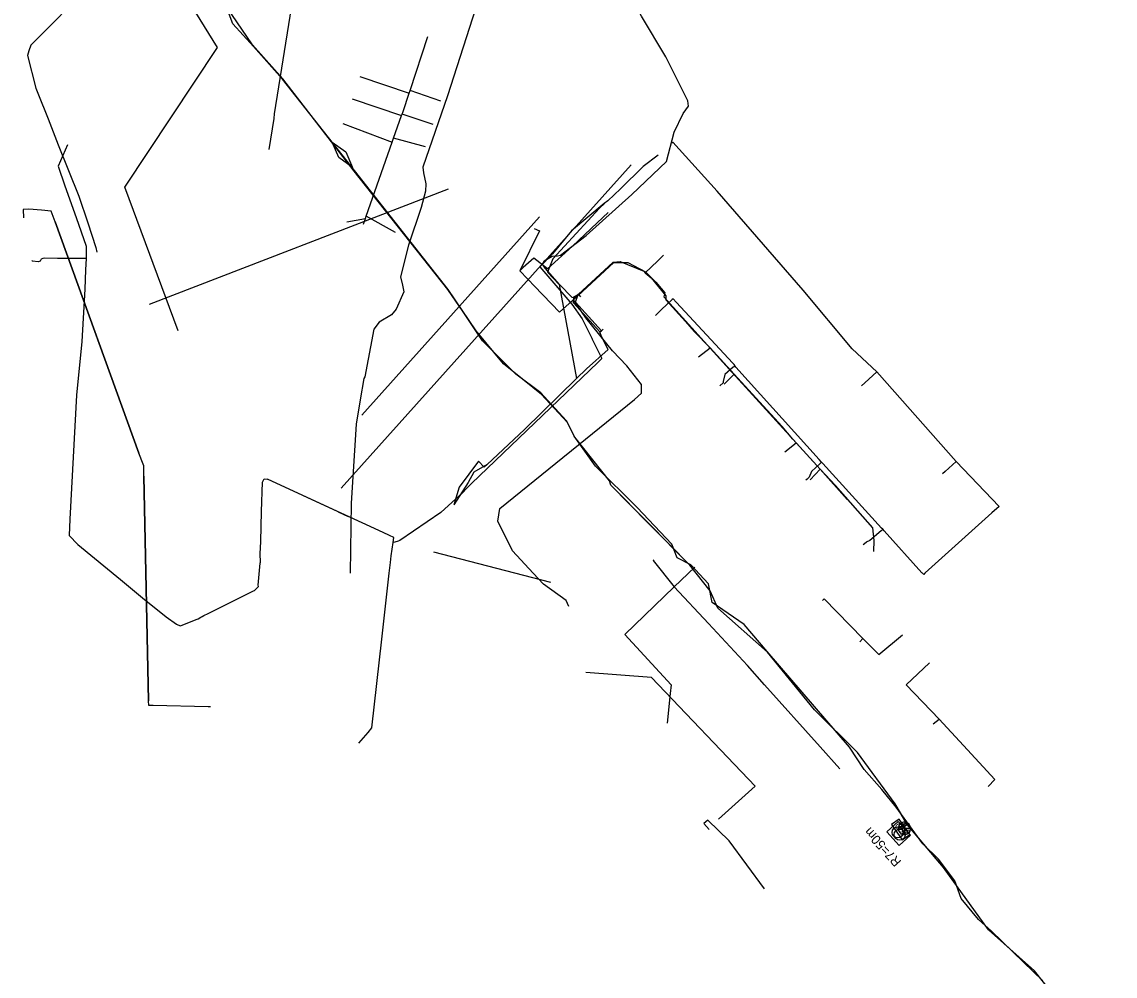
# Model space of a CAD drawing. Extents: x -748507 to -687366, y -1057342 to -1024924.
# Drawn here: x -744424.5 to -744188.5, y -1040087 to -1039880.9 of the extents above; entities that cross this region are included whole.
import ezdxf

# ---------------------------------------------------------------- set-up
doc = ezdxf.new("R2010")
doc.units = 0
for name, color, linetype in [('6kV - SŽDC', 7, 'Continuous'), ('DK + TKK - SŽDC', 7, 'Continuous'), ('Kanalizace - pražské vodovody a kanalizace', 7, 'Continuous'), ('NTL - PRAŽSKÁ PLYNÁRENSKÁ', 7, 'Continuous'), ('PRE - NN', 7, 'Continuous'), ('STL - PRAŽSKÁ PLYNÁRENSKÁ', 7, 'Continuous'), ('Telefonica O2', 7, 'Continuous'), ('TK+DOK_Pha Holešovice - Kralupy', 7, 'Continuous'), ('Vodovod - přežsko vodovody a kanalizace', 7, 'Continuous')]:
    doc.layers.add(name, color=color, linetype=linetype)

msp = doc.modelspace()

# ---------------------------------------------------------------- linework, layer by layer
at = {"layer": '6kV - SŽDC'}
for points in [[(-744368.25, -1039893.29), (-744374.48, -1039886.27), (-744378.97, -1039881.33), (-744380.56, -1039877.17), (-744384.32, -1039870.22), (-744391.86, -1039860.01), (-744394.99, -1039852.44), (-744396.08, -1039849.73), (-744402.91, -1039837.78), (-744404.95, -1039835.84), (-744408.32, -1039829.58), (-744409.64, -1039825.72), (-744411.8, -1039822.37), (-744414.1, -1039815.74), (-744417.59, -1039806.84), (-744420.96, -1039801.7), (-744422.82, -1039799.77), (-744423.64, -1039798.15), (-744424.52, -1039793.8)], [(-744326.42, -1039947.65), (-744332.5, -1039938.7), (-744355.33, -1039909.64), (-744368.25, -1039893.29)], [(-744353.16, -1039912.39), (-744356.11, -1039910.26), (-744357.5, -1039906.89), (-744354.55, -1039909.02), (-744353.16, -1039912.39)], [(-744242.63, -1040042.37), (-744245.85, -1040037.58), (-744263.57, -1040016.92), (-744268.59, -1040011.05), (-744275.48, -1040006.29), (-744276.28, -1040002.31), (-744280.07, -1039998.18), (-744283.01, -1039996.68), (-744284.21, -1039993.71), (-744291.7, -1039985.8), (-744300.69, -1039976.89), (-744305.31, -1039970.38), (-744306.8, -1039967.37), (-744312.32, -1039961.37), (-744320.56, -1039954.77), (-744326.42, -1039947.65)], [(-744204.19, -1040087.99), (-744208.25, -1040083.99), (-744215.17, -1040077.28), (-744217.99, -1040074.79), (-744221.69, -1040070.24), (-744223.08, -1040066.4), (-744226.63, -1040061.77), (-744230.03, -1040058.46), (-744235.77, -1040050.55), (-744238.86, -1040046.71), (-744242.63, -1040042.37)]]:
    msp.add_lwpolyline(points, dxfattribs=at)
at = {"layer": 'DK + TKK - SŽDC'}
for p, q in [((-744235.12, -1040053.09), (-744236.77, -1040054.25)), ((-744236.77, -1040054.25), (-744234.46, -1040057.55)), ((-744232.81, -1040056.39), (-744235.12, -1040053.09)), ((-744234.46, -1040057.55), (-744232.81, -1040056.39))]:
    msp.add_line(p, q, dxfattribs=at)
for points in [[(-744374.7, -1039885.89), (-744380.29, -1039877.76), (-744387.73, -1039866.25), (-744394.34, -1039856.01), (-744394.79, -1039852.71), (-744398.79, -1039844.27), (-744409.27, -1039827.53)], [(-744312.46, -1039961.08), (-744317.85, -1039957), (-744325.1, -1039949.82), (-744329.27, -1039943.58), (-744332.58, -1039938.75), (-744352.74, -1039913.16), (-744368.16, -1039893.24), (-744374.7, -1039885.89)], [(-744263.53, -1040017.02), (-744274.26, -1040007.58), (-744275.92, -1040003.81), (-744280.33, -1039998.25), (-744289.2, -1039989.22), (-744297.34, -1039980.99), (-744297.64, -1039980.08), (-744305.12, -1039970.61), (-744306.93, -1039967.07), (-744312.46, -1039961.08)], [(-744244.09, -1040038.7), (-744253.36, -1040029.48), (-744263.53, -1040017.02)], [(-743943.1, -1040375.98), (-743951.7, -1040366.67), (-743972.3, -1040343.88), (-744006.53, -1040306.88), (-744025.44, -1040285.45), (-744058.47, -1040248.87), (-744089.66, -1040214.01), (-744121.46, -1040179.2), (-744137.08, -1040162.07), (-744166.85, -1040129.04), (-744187.46, -1040107.76), (-744193.81, -1040101.14), (-744205.89, -1040085.9), (-744215.85, -1040077.02), (-744225.54, -1040063.55), (-744233.4, -1040054.23), (-744235.94, -1040049.83), (-744244.09, -1040038.7)], [(-744233.4, -1040054.23), (-744233.96, -1040054.74)]]:
    msp.add_lwpolyline(points, dxfattribs=at)
at = {"layer": 'Kanalizace - pražské vodovody a kanalizace'}
for p, q in [((-744369.95, -1039900.81), (-744364.16, -1039864.37)), ((-744351.52, -1039892.74), (-744340.9, -1039896.31)), ((-744334.07, -1039898.04), (-744340.71, -1039895.74)), ((-744353.17, -1039897.57), (-744342.52, -1039901.13)), ((-744335.7, -1039903.1), (-744342.42, -1039900.85)), ((-744355.23, -1039902.91), (-744344.55, -1039906.9)), ((-744337.34, -1039907.94), (-744344.25, -1039906.05)), ((-744312.38, -1039933.47), (-744292.95, -1039911.81)), ((-744396.95, -1039941.87), (-744332.39, -1039917)), ((-744354.35, -1039924.09), (-744350.33, -1039923.37)), ((-744351.15, -1039965.85), (-744312.75, -1039923.06)), ((-744343.86, -1039926.42), (-744350.16, -1039922.9)), ((-744355.57, -1039981.62), (-744312.38, -1039933.47)), ((-744279.23, -1039998.72), (-744283.66, -1040002.95)), ((-744283.66, -1040002.95), (-744294.37, -1040013.23)), ((-744276.3, -1040010.86), (-744283.66, -1040002.95)), ((-744267.85, -1040019.95), (-744276.3, -1040010.86)), ((-744294.37, -1040013.23), (-744284.34, -1040024.1)), ((-744243.61, -1040014.83), (-744242.93, -1040014.07)), ((-744242.93, -1040014.07), (-744239.5, -1040017.57)), ((-744239.5, -1040017.57), (-744234.38, -1040013.34)), ((-744233.56, -1040024.13), (-744228.54, -1040019.35)), ((-744264.15, -1040024.07), (-744267.85, -1040019.95)), ((-744284.34, -1040024.1), (-744284.52, -1040025.94)), ((-744252.13, -1040037.49), (-744264.15, -1040024.07)), ((-744226.45, -1040031.5), (-744233.56, -1040024.13)), ((-744284.52, -1040025.94), (-744285.22, -1040032.41)), ((-744227.78, -1040032.55), (-744226.45, -1040031.5)), ((-744247.91, -1040042.21), (-744252.13, -1040037.49))]:
    msp.add_line(p, q, dxfattribs=at)
for points in [[(-744390.78, -1039947.69), (-744402.3, -1039916.65), (-744382.3, -1039886.5), (-744399.85, -1039858.04)], [(-744342.22, -1039900.28), (-744340.9, -1039896.31), (-744340.71, -1039895.74), (-744336.86, -1039884.1)], [(-744371.11, -1039908.47), (-744370.08, -1039901.83), (-744369.95, -1039900.81)], [(-744350.76, -1039924.6), (-744350.33, -1039923.37), (-744350.16, -1039922.9), (-744344.55, -1039906.9), (-744344.25, -1039906.05), (-744342.52, -1039901.13), (-744342.42, -1039900.85), (-744342.22, -1039900.28)], [(-744288.06, -1039997.09), (-744288.21, -1039997.28), (-744283.66, -1040002.95)], [(-744251.64, -1040005.87), (-744251.28, -1040005.53), (-744242.93, -1040014.07)], [(-744215.86, -1040046.04), (-744214.46, -1040044.56), (-744221.18, -1040037.24), (-744226.45, -1040031.5)]]:
    msp.add_lwpolyline(points, dxfattribs=at)
at = {"layer": 'NTL - PRAŽSKÁ PLYNÁRENSKÁ'}
for p, q in [((-744417.34, -1039924.11), (-744399.23, -1039974.04)), ((-744398.17, -1039979.02), (-744397.15, -1040027.58))]:
    msp.add_line(p, q, dxfattribs=at)
for points in [[(-744398.35, -1039976.46), (-744399.23, -1039974.04), (-744417.34, -1039924.11), (-744418.18, -1039921.79), (-744420.28, -1039921.61), (-744422.98, -1039921.38), (-744424.22, -1039921.45), (-744424.18, -1039923.22)], [(-744383.78, -1040028.84), (-744384.32, -1040028.83), (-744396.14, -1040028.59), (-744397.14, -1040028.58), (-744397.15, -1040027.58), (-744398.17, -1039979.02), (-744398.22, -1039976.84), (-744398.35, -1039976.46)], [(-744264.2, -1040068.15), (-744271.84, -1040057.78), (-744276.45, -1040053.34), (-744277.26, -1040054.08), (-744276.11, -1040055.33)]]:
    msp.add_lwpolyline(points, dxfattribs=at)
at = {"layer": 'PRE - NN'}
for points in [[(-744297.94, -1039922.07), (-744300.34, -1039924.35), (-744305.67, -1039929.35), (-744311.01, -1039934.25), (-744313.97, -1039931.97), (-744316.26, -1039934.01), (-744317.02, -1039934.69)], [(-744313.89, -1039925.57), (-744312.73, -1039926.07), (-744317.02, -1039934.69)], [(-744306.4, -1040007.18), (-744306.98, -1040005.86), (-744311.91, -1040002.38), (-744314.11, -1040000), (-744318.56, -1039995.2), (-744321.75, -1039988.73), (-744321.32, -1039986.03), (-744292.28, -1039962.52), (-744290.77, -1039961.13), (-744290.71, -1039959.25), (-744293.88, -1039955.24), (-744296.99, -1039951.95), (-744302.77, -1039944.84), (-744305.4, -1039940.99), (-744296.74, -1039932.93), (-744293.7, -1039932.91), (-744289.85, -1039934.89), (-744287.62, -1039937.18), (-744285.67, -1039939.44), (-744285.91, -1039940.31), (-744271.16, -1039956.65), (-744252.15, -1039977.55), (-744246.3, -1039984.05)], [(-744317.02, -1039934.69), (-744313.69, -1039938.18), (-744312.26, -1039939.65), (-744311.97, -1039939.95), (-744308.42, -1039943.6), (-744304.3, -1039939.88), (-744303.93, -1039940.32)]]:
    msp.add_lwpolyline(points, dxfattribs=at)
at = {"layer": 'STL - PRAŽSKÁ PLYNÁRENSKÁ'}
for p, q in [((-744410.64, -1039931.09), (-744410.65, -1039932.02)), ((-744410.62, -1039930.74), (-744410.64, -1039931.09)), ((-744286.85, -1039943.47), (-744287.73, -1039944.35)), ((-744300.14, -1039954.46), (-744327.46, -1039980.63)), ((-744254.57, -1039979.29), (-744254.66, -1039979.39)), ((-744356.25, -1039986.73), (-744371.52, -1039979.66)), ((-744356.24, -1039986.73), (-744354.05, -1039987.74)), ((-744344.36, -1039993.36), (-744344.27, -1039993.34)), ((-744343.98, -1039993.26), (-744344.27, -1039993.34)), ((-744343.28, -1039993.06), (-744343.98, -1039993.26))]:
    msp.add_line(p, q, dxfattribs=at)
for points in [[(-744414.68, -1039907.51), (-744416.71, -1039912.11), (-744415.21, -1039916.31), (-744412.78, -1039923.15), (-744410.63, -1039929.34), (-744410.62, -1039930.74)], [(-744213.5, -1039985.59), (-744222.78, -1039975.84), (-744239.93, -1039956.51), (-744245.24, -1039951.55), (-744255.82, -1039938.86), (-744274.38, -1039917.48), (-744283.94, -1039906.92), (-744284.2, -1039907.12)], [(-744287.14, -1039909.7), (-744290.4, -1039912.17), (-744295.29, -1039917), (-744298.04, -1039919.6), (-744298.8, -1039920.16), (-744305.84, -1039926.05), (-744309.95, -1039931), (-744312.68, -1039933.82), (-744305.76, -1039941.92), (-744303.55, -1039945.05), (-744301.38, -1039949.41)], [(-744410.65, -1039932.02), (-744416.83, -1039932.02), (-744419.54, -1039931.99), (-744419.97, -1039932.01), (-744420.32, -1039932.16), (-744420.54, -1039932.59), (-744420.99, -1039932.73), (-744422.23, -1039932.62), (-744422.4, -1039932.49)], [(-744410.65, -1039932.02), (-744410.79, -1039934.48), (-744410.95, -1039938.65), (-744411.56, -1039949.94), (-744412.71, -1039961.54), (-744414.14, -1039988.32), (-744414.33, -1039991.88), (-744412.47, -1039993.83), (-744403.24, -1040001.34), (-744398.45, -1040005.29), (-744393.34, -1040009.4), (-744391.16, -1040011.02), (-744390.34, -1040011.37), (-744389.9, -1040011.19), (-744386.86, -1040010.01), (-744386.49, -1040009.83), (-744385.87, -1040009.51), (-744385.58, -1040009.35), (-744385.21, -1040009.14), (-744384.3, -1040008.67), (-744381.97, -1040007.58), (-744374.51, -1040003.8), (-744374.3, -1040003.71), (-744373.46, -1040002.89), (-744373.48, -1040002.57), (-744373.09, -1039997.86), (-744372.98, -1039997.64), (-744373.07, -1039995.85), (-744372.94, -1039993.17), (-744372.76, -1039986.7), (-744372.6, -1039980.37), (-744372.19, -1039979.65), (-744371.52, -1039979.66)], [(-744283.9, -1039940.74), (-744284.14, -1039940.9), (-744286.4, -1039943.02), (-744286.85, -1039943.47)], [(-744270.74, -1039954.93), (-744271.01, -1039954.63), (-744283.28, -1039941.43), (-744283.9, -1039940.74)], [(-744329.26, -1039982.47), (-744328.56, -1039981.75), (-744328.5, -1039981.68), (-744327.8, -1039980.96), (-744327.46, -1039980.63), (-744300.14, -1039954.46), (-744299.71, -1039954.04), (-744299.28, -1039953.63), (-744299.32, -1039953.54), (-744301.38, -1039949.41)], [(-744270.54, -1039955.26), (-744270.93, -1039955.51), (-744272.71, -1039957.07), (-744273.07, -1039958.58)], [(-744213.5, -1039985.59), (-744215.1, -1039986.95), (-744229.5, -1039999.93), (-744229.56, -1040000), (-744229.79, -1040000.26), (-744230.08, -1040000), (-744230.2, -1039999.9), (-744238.34, -1039990.84), (-744238.62, -1039990.49), (-744238.9, -1039990.29), (-744251.61, -1039976.28), (-744251.86, -1039976.02), (-744252.35, -1039975.44), (-744270.35, -1039955.48), (-744270.54, -1039955.26), (-744270.74, -1039954.93)], [(-744239.93, -1039956.51), (-744242.54, -1039958.89), (-744243.25, -1039959.52)], [(-744273.07, -1039958.58), (-744273.13, -1039958.86), (-744273.84, -1039959.56)], [(-744251.86, -1039976.02), (-744252.13, -1039976.31), (-744254, -1039978), (-744254.57, -1039979.29)], [(-744222.78, -1039975.84), (-744225.17, -1039978.02), (-744225.76, -1039978.57)], [(-744344.36, -1039993.36), (-744344.21, -1039992.27), (-744345.12, -1039991.85), (-744346.48, -1039991.22), (-744355.61, -1039987.03), (-744371.52, -1039979.66)], [(-744254.66, -1039979.39), (-744255, -1039979.7), (-744255.26, -1039979.93)], [(-744329.26, -1039982.47), (-744334.06, -1039986.86), (-744342.91, -1039992.94), (-744343.28, -1039993.06)], [(-744238.62, -1039990.49), (-744238.99, -1039990.85), (-744241.45, -1039992.92), (-744242.24, -1039993.33)], [(-744351.77, -1040036.67), (-744349.75, -1040034.38), (-744348.98, -1040033.41), (-744346.81, -1040014.23), (-744345.2, -1040000), (-744344.95, -1039997.72), (-744344.78, -1039996.22), (-744344.36, -1039993.36)], [(-744242.24, -1039993.33), (-744242.26, -1039993.34), (-744242.88, -1039993.89)]]:
    msp.add_lwpolyline(points, dxfattribs=at)
at = {"layer": 'Telefonica O2'}
for points in [[(-744304.3, -1039855.63), (-744305.07, -1039854.44), (-744307.1, -1039853.62), (-744311.94, -1039853.03), (-744316.56, -1039854.15), (-744319.15, -1039856.63), (-744321.44, -1039860.62), (-744323.74, -1039869.28), (-744327.19, -1039880.13), (-744332.61, -1039896.92), (-744337.94, -1039912.34), (-744337.79, -1039913.56), (-744337.28, -1039915.93), (-744337.36, -1039917.5), (-744338.34, -1039921.02), (-744341.03, -1039929.15), (-744342.79, -1039935.99), (-744342.35, -1039937.79), (-744342.05, -1039939.2), (-744343.67, -1039942.97), (-744344.7, -1039944.19), (-744347.36, -1039945.79), (-744348.5, -1039947.32), (-744350.45, -1039957.56)], [(-744304.44, -1039939.84), (-744305.26, -1039940.56), (-744305.68, -1039940.47), (-744308.46, -1039937.67), (-744311.56, -1039934.15), (-744312.14, -1039933.23), (-744311.76, -1039932.57), (-744310.02, -1039931.5), (-744308.85, -1039931.46), (-744308.22, -1039931.29), (-744302.7, -1039927.08), (-744292.8, -1039918.21), (-744285.34, -1039911.12), (-744283.65, -1039904.76), (-744281.77, -1039900.69), (-744280.6, -1039899.12), (-744280.75, -1039897.97), (-744285.49, -1039888.46), (-744290.77, -1039879.69), (-744294.83, -1039872.09), (-744298.52, -1039863.7), (-744301.65, -1039857.36), (-744303.05, -1039856.53)], [(-744298.72, -1039920.16), (-744299.81, -1039921.15)], [(-744299.81, -1039921.15), (-744309.91, -1039932.12)], [(-744285.96, -1039931.32), (-744287.27, -1039932.58), (-744289.92, -1039935.13)], [(-744309.91, -1039932.12), (-744311.03, -1039934.98), (-744308.52, -1039937.64), (-744304.74, -1039957.94)], [(-744304.44, -1039939.84), (-744296.86, -1039932.86), (-744295.33, -1039932.68), (-744290.24, -1039934.77)], [(-744287.27, -1039932.58), (-744289.92, -1039935.13)], [(-744290.24, -1039934.77), (-744289.92, -1039935.13)], [(-744289.92, -1039935.13), (-744288.67, -1039936.21), (-744285.47, -1039940.13), (-744285.45, -1039940.98), (-744281.21, -1039945.65), (-744279.35, -1039947.78), (-744275.94, -1039951.35)], [(-744308.46, -1039937.67), (-744305.68, -1039940.47)], [(-744299.7, -1039947.89), (-744305.4, -1039941.64), (-744305.33, -1039940.33), (-744304.44, -1039939.84)], [(-744299.4, -1039947.67), (-744305.01, -1039941.44), (-744304.44, -1039939.84)], [(-744304.74, -1039957.94), (-744302.61, -1039955.85), (-744297.92, -1039951.72), (-744299.34, -1039948.88), (-744299.7, -1039947.89), (-744299.4, -1039947.67)], [(-744299.4, -1039947.67), (-744299.02, -1039947.27)], [(-744278.43, -1039953.24), (-744275.94, -1039951.35)], [(-744270.7, -1039957.01), (-744275.94, -1039951.35)], [(-744350.45, -1039957.56), (-744350.69, -1039957.92), (-744351.5, -1039962.57), (-744352.31, -1039967.79), (-744353.44, -1039984.89), (-744353.65, -1040000)], [(-744304.74, -1039957.94), (-744315.97, -1039968.95)], [(-744315.97, -1039968.95), (-744304.74, -1039957.94)], [(-744270.7, -1039957.01), (-744272.91, -1039959.2)], [(-744258.05, -1039971.02), (-744260.39, -1039968.29), (-744263.57, -1039964.81), (-744270.7, -1039957.01)], [(-744315.97, -1039968.95), (-744324.03, -1039976.55), (-744326.95, -1039978.21), (-744328.13, -1039980.39), (-744331.29, -1039985.2)], [(-744315.97, -1039968.95), (-744324.03, -1039976.55), (-744324.73, -1039977.1), (-744325.96, -1039975.77), (-744330.09, -1039981.43)], [(-744259.76, -1039973.78), (-744257.31, -1039971.84)], [(-744257.31, -1039971.84), (-744258.05, -1039971.02)], [(-744252.16, -1039977.5), (-744257.31, -1039971.84)], [(-744252.16, -1039977.5), (-744254.29, -1039979.81)], [(-744240.56, -1039995.29), (-744240.49, -1039992.96), (-744240.82, -1039990.23), (-744248.85, -1039981.08), (-744252.16, -1039977.5)], [(-744330.09, -1039981.43), (-744331.29, -1039985.2)]]:
    msp.add_lwpolyline(points, dxfattribs=at)
at = {"layer": 'TK+DOK_Pha Holešovice - Kralupy'}
for p, q in [((-744235.24, -1040054.65), (-744233.95, -1040054.72)), ((-744234.88, -1040054.1), (-744233.92, -1040054.15)), ((-744236.01, -1040057.05), (-744236.03, -1040057.01)), ((-744235.32, -1040055.02), (-744235.32, -1040055.02)), ((-744235.32, -1040055.02), (-744235.32, -1040055.02)), ((-744234.03, -1040056.45), (-744234.03, -1040056.45)), ((-744234.01, -1040055.99), (-744233.01, -1040056.04)), ((-744233.98, -1040055.41), (-744232.68, -1040055.48)), ((-744232.62, -1040055.16), (-744232.62, -1040055.16)), ((-744232.62, -1040055.16), (-744232.62, -1040055.16))]:
    msp.add_line(p, q, dxfattribs=at)
for points in [[(-744374.7, -1039885.89), (-744380.29, -1039877.76), (-744387.73, -1039866.25), (-744394.34, -1039856.01), (-744394.79, -1039852.71), (-744398.79, -1039844.27), (-744409.27, -1039827.53)], [(-744225.54, -1040063.55), (-744233.23, -1040054.44), (-744235.94, -1040049.83), (-744244.09, -1040038.7), (-744253.36, -1040029.48), (-744263.53, -1040017.02), (-744274.26, -1040007.58), (-744275.92, -1040003.81), (-744280.33, -1039998.25), (-744289.2, -1039989.23), (-744297.34, -1039980.99), (-744297.64, -1039980.08), (-744305.12, -1039970.61), (-744306.93, -1039967.06), (-744312.46, -1039961.08), (-744317.85, -1039957), (-744325.1, -1039949.82), (-744329.27, -1039943.58), (-744332.57, -1039938.75), (-744352.74, -1039913.16), (-744368.16, -1039893.24), (-744374.7, -1039885.89), (-744380.29, -1039877.76)], [(-744263.53, -1040017.02), (-744274.26, -1040007.58), (-744275.92, -1040003.81), (-744280.33, -1039998.25), (-744289.2, -1039989.23), (-744297.34, -1039980.99), (-744297.64, -1039980.08), (-744305.12, -1039970.61), (-744306.93, -1039967.06), (-744312.46, -1039961.08), (-744317.85, -1039957), (-744325.1, -1039949.82), (-744329.27, -1039943.58), (-744332.57, -1039938.75), (-744352.74, -1039913.16), (-744368.16, -1039893.24), (-744374.7, -1039885.89)], [(-744235.94, -1040049.83), (-744244.09, -1040038.7), (-744253.36, -1040029.48), (-744263.53, -1040017.02)], [(-743943.1, -1040375.98), (-743951.7, -1040366.67), (-743972.3, -1040343.88), (-744006.53, -1040306.88), (-744025.44, -1040285.45), (-744058.47, -1040248.87), (-744089.66, -1040214.01), (-744121.46, -1040179.2), (-744137.08, -1040162.06), (-744166.85, -1040129.04), (-744187.46, -1040107.76), (-744193.81, -1040101.14), (-744205.89, -1040085.9), (-744215.85, -1040077.02), (-744225.54, -1040063.55), (-744233.23, -1040054.44), (-744235.94, -1040049.83)], [(-744233.9, -1040053.75), (-744233.97, -1040055.09), (-744235.32, -1040055.02)], [(-744232.62, -1040055.16), (-744233.97, -1040055.1), (-744234.03, -1040056.45)], [(-744193.81, -1040101.14), (-744205.89, -1040085.9), (-744215.85, -1040077.02), (-744225.54, -1040063.55)]]:
    msp.add_lwpolyline(points, dxfattribs=at)
msp.add_lwpolyline([(-744235.1, -1040058.81), (-744237.77, -1040055.85), (-744235.3, -1040053.62), (-744232.63, -1040056.58)], close=True, dxfattribs=at)
for centre in [(-744235.44, -1040055.97), (-744234.98, -1040056.45)]:
    msp.add_circle(centre, 1.2, dxfattribs=at)
for centre, start, end in [((-744233.97, -1040055.09), 86.6074, 176.8445), ((-744233.97, -1040055.1), 357.5597, 86.9257), ((-744233.97, -1040055.09), 176.8458, 267.6352), ((-744233.97, -1040055.1), 267.3226, 357.5597)]:
    msp.add_arc(centre, 1.35, start, end, dxfattribs=at)
at = {"layer": 'Vodovod - přežsko vodovody a kanalizace'}
msp.add_line((-744310.29, -1040002.02), (-744335.54, -1039995.45), dxfattribs=at)
for points in [[(-744400.76, -1039858.71), (-744400.06, -1039859.65), (-744399.82, -1039860.78), (-744399.77, -1039862), (-744400.16, -1039863.12), (-744401.17, -1039864.23), (-744401.3, -1039864.41), (-744401.5, -1039864.6), (-744405.57, -1039868.73), (-744409.78, -1039873.01), (-744413.98, -1039877.29), (-744418.19, -1039881.56), (-744422.6, -1039886), (-744423.05, -1039887.17), (-744423.3, -1039888.22), (-744421.49, -1039895.28), (-744421.08, -1039896.31), (-744418.86, -1039901.89), (-744416.65, -1039907.46), (-744414.43, -1039913.04), (-744412.21, -1039918.61), (-744410.29, -1039924.3), (-744408.56, -1039929.64), (-744408.32, -1039930.64)], [(-744274.11, -1040053.1), (-744266.2, -1040045.96), (-744288.56, -1040022.51), (-744302.73, -1040021.47)]]:
    msp.add_lwpolyline(points, dxfattribs=at)

# ---------------------------------------------------------------- texts
at = {"layer": 'DK + TKK - SŽDC'}
msp.add_text('KO', height=1.344, rotation=125, dxfattribs=at).set_placement((-744233.57, -1040055.87))
at = {"layer": 'TK+DOK_Pha Holešovice - Kralupy'}
msp.add_text('R7=50m', height=2, rotation=132.0809, dxfattribs=at).set_placement((-744234.53, -1040062.25))

doc.saveas('drawing.dxf')
